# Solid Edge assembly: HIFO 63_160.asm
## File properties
Title: Zylinder
Author: ahadarics
Template: iso assembly.asm
Last saved by: ahadarics
Revision: 50
Application: Solid Edge
Username: ahadarics
Dokumentum tartalom típus: 1
Document Number: HIFO 63/160
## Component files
Kit_2.par
Kit_1.par
Profilrohr 63_160.par
Kolbenstange 63_160.par
Mutter.par
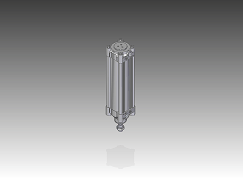
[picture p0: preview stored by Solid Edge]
